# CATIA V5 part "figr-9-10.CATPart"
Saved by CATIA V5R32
Part number: Part1
Bounding box of the stored display mesh (mm): x -15.705 to 98.193, y 0 to 272.268, z -20.723 to 20.723
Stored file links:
  D:\PROJECTS\Project 2022\CATIA V5 6R 2022\Resources\Part Files\c09_catia_v5_6r2022_prt\c09_catia_v5_6r2022_prt\figr-9-10.CATPart
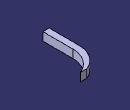
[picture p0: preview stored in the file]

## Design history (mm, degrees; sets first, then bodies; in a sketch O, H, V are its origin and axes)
Body1 (main body)
  Sketch1 on xy-plane, origin (0, 0, 0), H (1, 0, 0), V (0, 1, 0)
    line L1 (0, 0) -> (0, 150)
    arc A1 centre (131.8599, 150) radius 131.8599 from (0, 150) to (82.4884, 272.2681) cw
    length L1 = 150
    tangency: A1 L1
  Sketch2 on zx-plane, origin (0, 0, 0), H (-1, 0, 0), V (0, 0, 1)
    line L1 (15.7048, 20.7231) -> (15.7048, -20.7231)
    line L2 (15.7048, -20.7231) -> (-15.7048, -20.7231)
    line L3 (-15.7048, -20.7231) -> (-15.7048, 20.7231)
    line L4 (-15.7048, 20.7231) -> (15.7048, 20.7231)
    vertical: L1 V, L3 V
    horizontal: L2 H, L4 H
    equidistance: L1 L3 O, L2 L4 O
  Rib1: profile Sketch2, centre curve Sketch1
